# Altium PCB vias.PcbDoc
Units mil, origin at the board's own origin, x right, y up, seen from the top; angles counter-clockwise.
Board outline 1574.8 x 984.25 mil, 6 copper layers (Top Layer, Internal Plane 1, Mid-Layer 2, Internal Plane 2, Mid-Layer 4, Bottom Layer), stack 60.63 mil thick; 4 components, 3 nets, 8 pads, 2 vias.
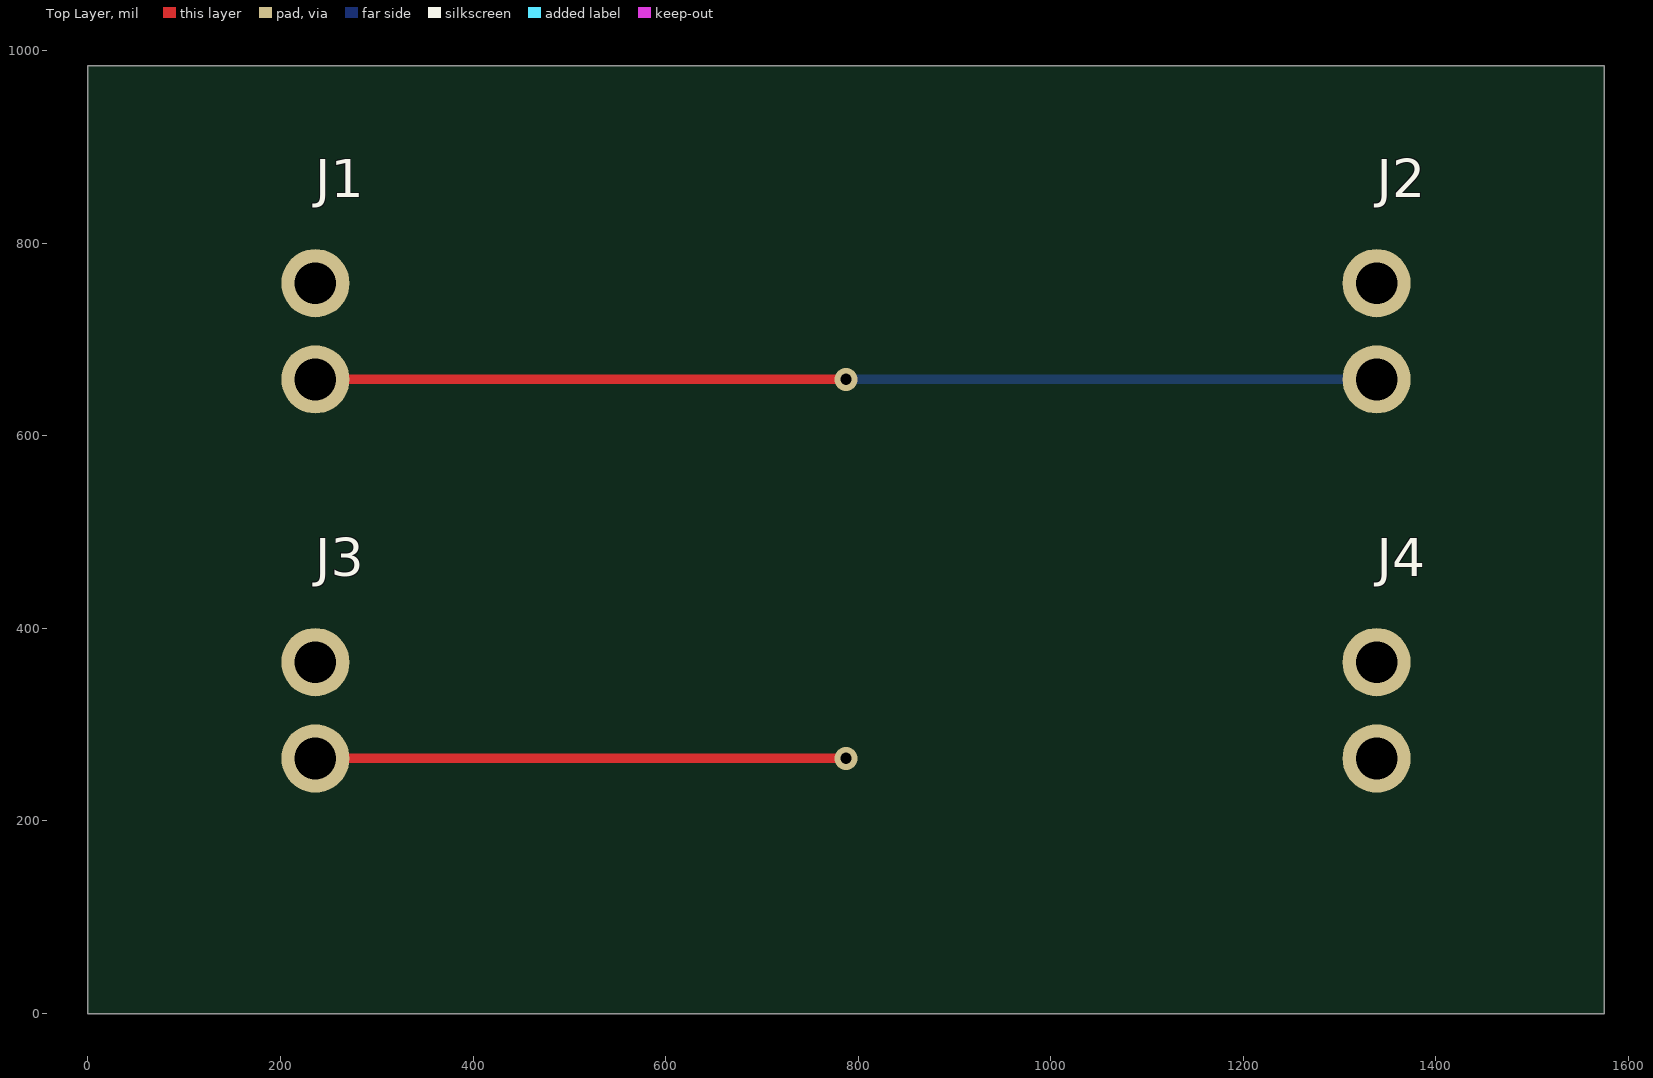
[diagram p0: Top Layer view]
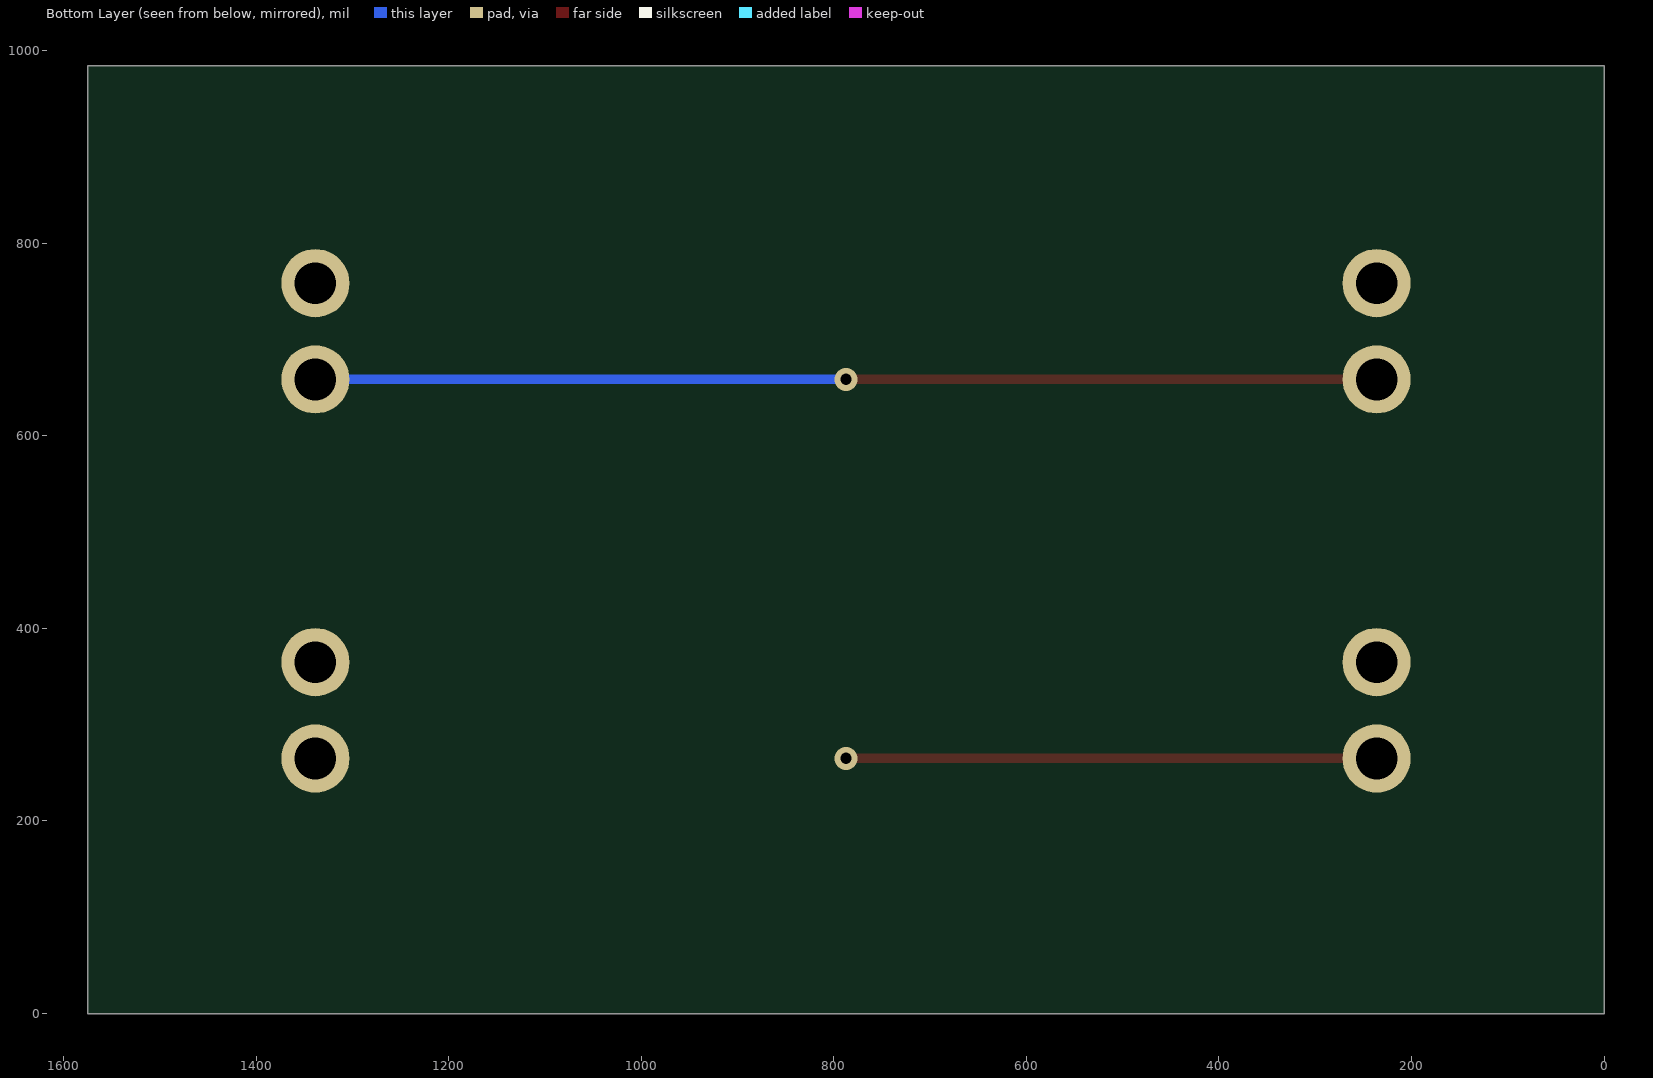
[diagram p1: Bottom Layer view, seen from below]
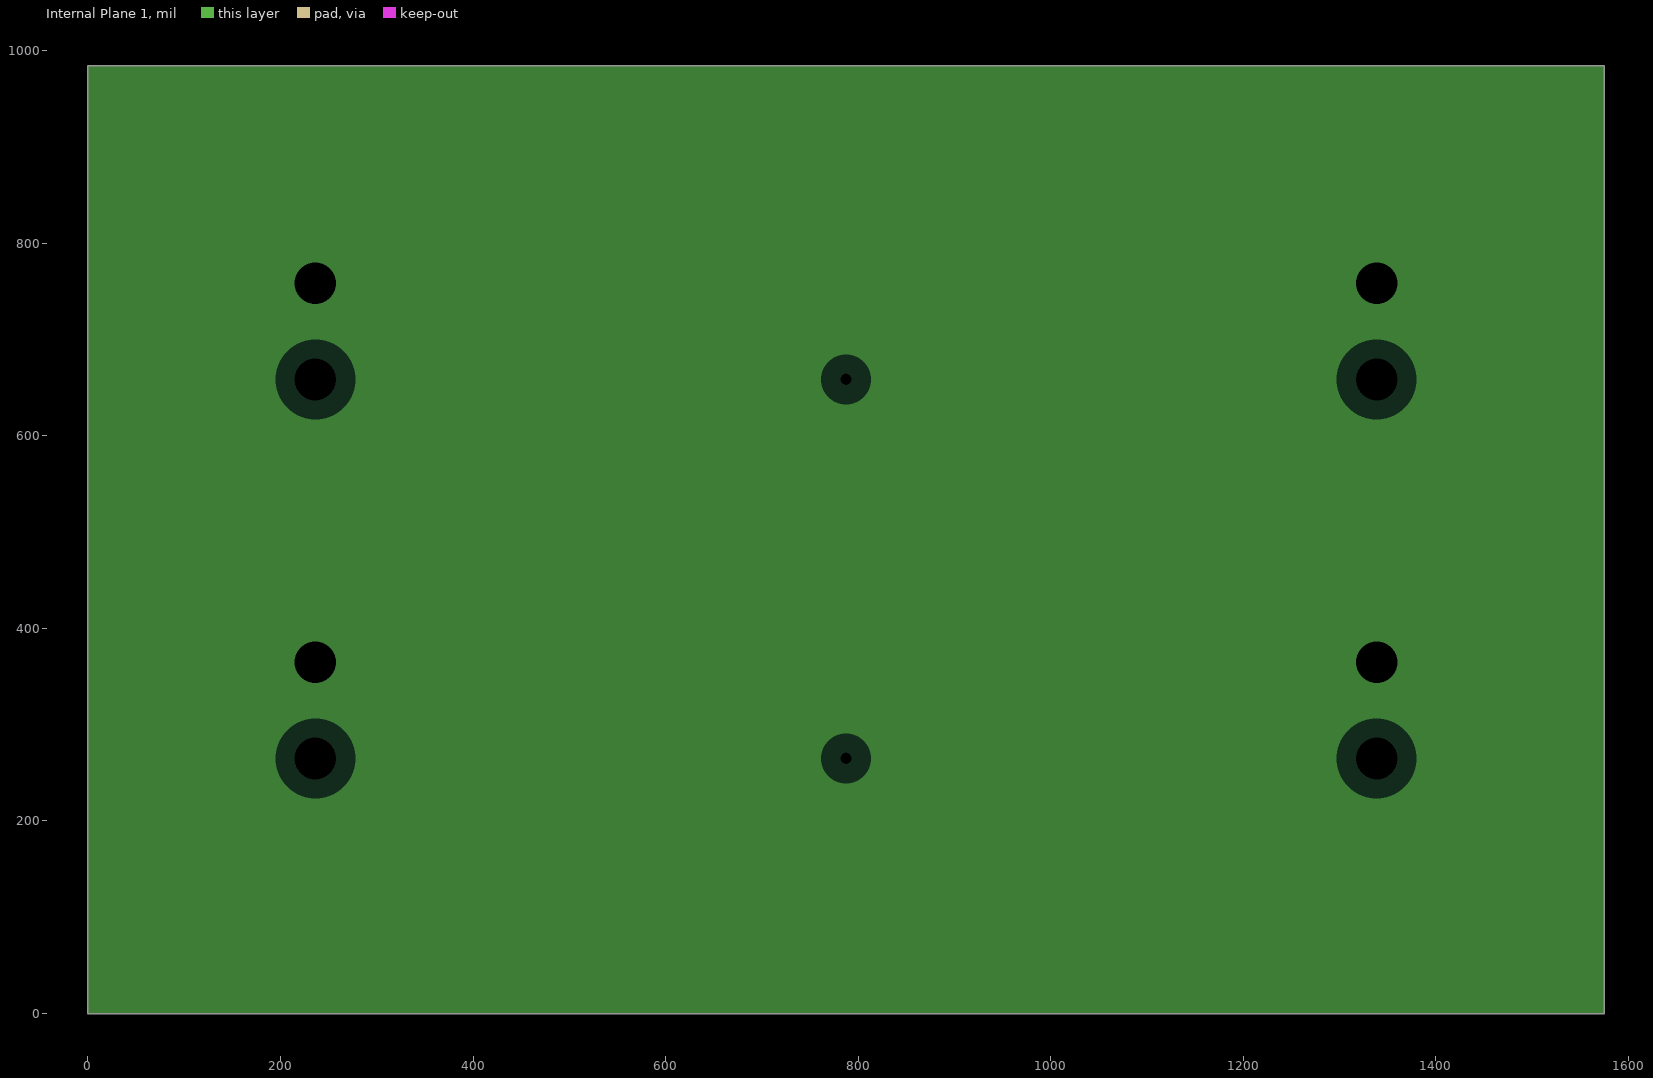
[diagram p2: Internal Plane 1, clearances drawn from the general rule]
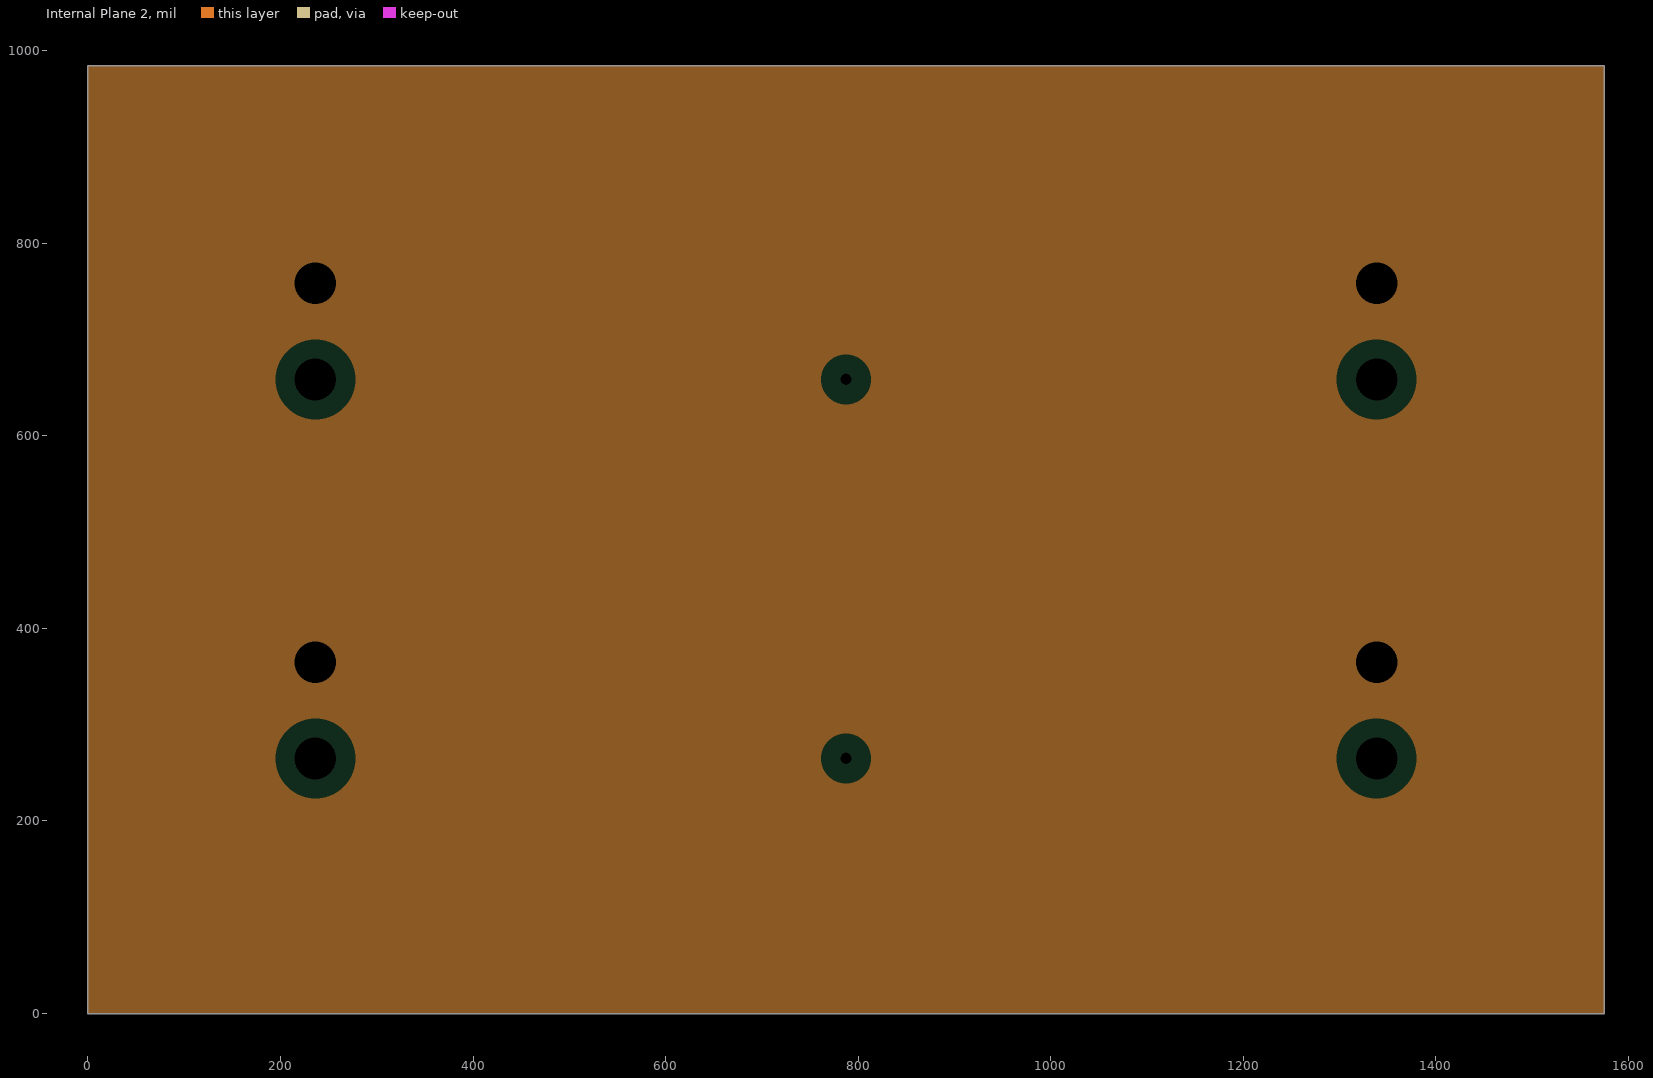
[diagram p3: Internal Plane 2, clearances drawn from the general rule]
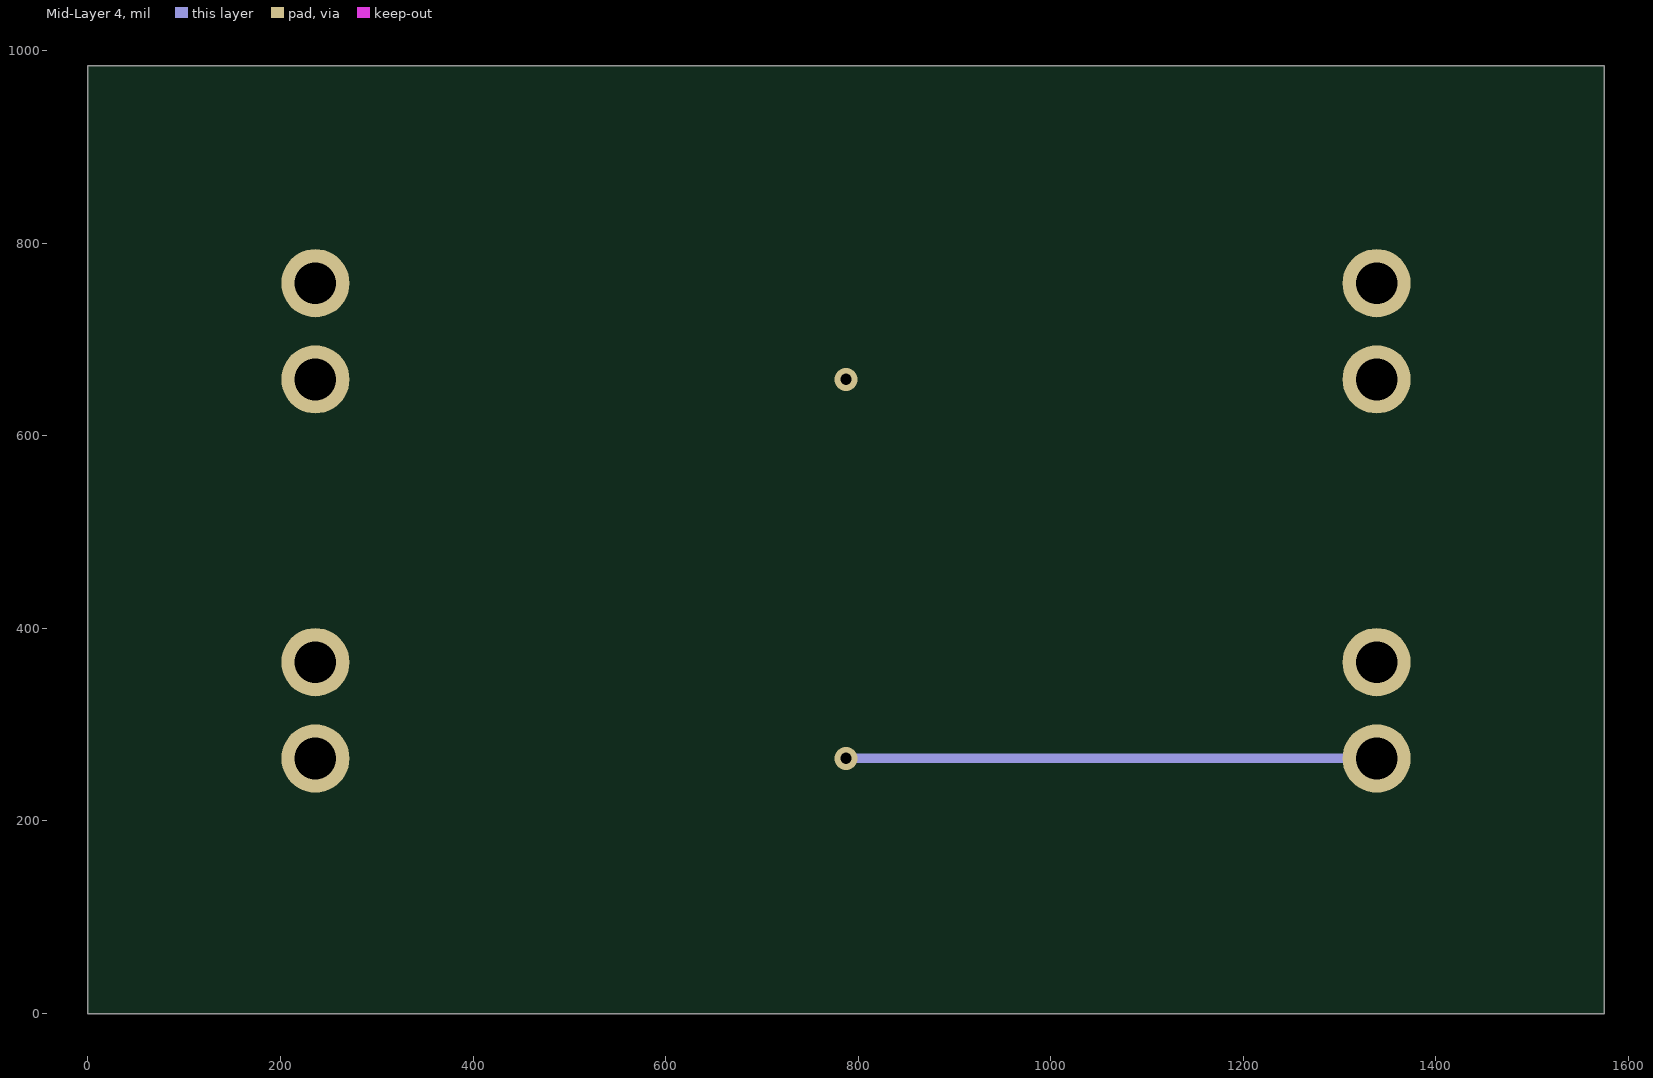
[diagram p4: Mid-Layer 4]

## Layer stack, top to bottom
Top Solder: solder mask 0.4, Solder Resist, Dk 3.5
Top Layer: signal copper 1.378
Dielectric 1: prepreg 7.874, FR-4, Dk 4.5
Internal Plane 1: plane copper 0.689, net GND
Dielectric 2: core 7.874, FR-4, Dk 4.5
Mid-Layer 2: signal copper 0.689
Dielectric 3: prepreg 23.622, FR-4, Dk 4.5
Internal Plane 2: plane copper 0.689, net GND
Dielectric 4: core 7.874, FR-4, Dk 4.5
Mid-Layer 4: signal copper 0.689
Dielectric 5: prepreg 7.874, FR-4, Dk 4.5
Bottom Layer: signal copper 1.378
Bottom Solder: solder mask 0.4, Solder Resist, Dk 3.5

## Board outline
0,984.25 1574.8,984.25 1574.8,0 0,0

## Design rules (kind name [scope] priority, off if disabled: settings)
Clearance [All] p1: gap=7.87 ignorepadtopadclearanceinfootprint=FALSE
RoutingVias [All] p1: holewidth=11.81 width=23.62 viastyle="Through Hole" minholewidth=11.81 minwidth=23.62 maxholewidth=11.81 maxwidth=23.62
Width [All] p1: maxlimit=9.84 minlimit=9.84 preferedwidth=9.84

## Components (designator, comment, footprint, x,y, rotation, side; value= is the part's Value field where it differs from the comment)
J1 "SIG_IN" Header_1x2_P2.54 236.22,708.66 r0 top
J2 "SIG_OUT" Header_1x2_P2.54 1338.58,708.66 r0 top
J3 "AUX_IN" Header_1x2_P2.54 236.22,314.96 r0 top
J4 "AUX_OUT" Header_1x2_P2.54 1338.58,314.96 r0 top

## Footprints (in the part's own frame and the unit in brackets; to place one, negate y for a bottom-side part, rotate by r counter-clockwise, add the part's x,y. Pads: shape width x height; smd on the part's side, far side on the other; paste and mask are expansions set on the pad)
Header_1x2_P2.54 [mm]
  round 1.8 hole 1.1: 1(0,-1.27) 2(0,1.27)

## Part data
J1 J2 J3 J4: library part Connector_2

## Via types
v1: diameter 23.62, hole 11.81, Top Layer to Bottom Layer, 2 vias

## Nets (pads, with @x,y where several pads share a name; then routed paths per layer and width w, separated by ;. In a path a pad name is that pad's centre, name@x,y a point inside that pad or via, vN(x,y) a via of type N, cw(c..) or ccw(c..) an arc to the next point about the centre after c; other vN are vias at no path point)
AUX: J3.1 J4.1 | length 1102.4
  Top Layer w9.84: J3.1 v1(787.4,264.96)
  Mid-Layer 4 w9.84: v1(787.4,264.96) J4.1
GND: J1.2 J2.2 J3.2 J4.2
SIG: J1.1 J2.1 | length 1102.4
  Top Layer w9.84: J1.1 v1(787.4,658.66)
  Bottom Layer w9.84: v1(787.4,658.66) J2.1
